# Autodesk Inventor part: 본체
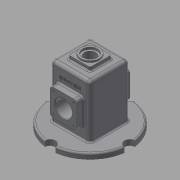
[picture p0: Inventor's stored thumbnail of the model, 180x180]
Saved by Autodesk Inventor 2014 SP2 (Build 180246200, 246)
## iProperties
Created: 2018-07
Part Number: 본체
Material: Generic
Document SubType Name: Modeling
Designer: 거성
Density: 1 g/cm^3
Appearance: Default
Author: 거성
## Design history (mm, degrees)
sketch "스케치1"
  geometry: L1 (-37, 37)-(37, 37); L2 (37, 37)-(37, -37); L3 (37, -37)-(-37, -37); L4 (-37, -37)-(-37, 37); 3 further points
  constraints: 8 end point, 2 midpoint, 2 parallel, 1 horizontal, 1 horizontal alignment, 1 perpendicular, 1 vertical alignment
  dimensions: "d0" = 74 distance of L1.start L1.end; "d1" = 74 distance of L1.end L2.end
extrude "돌출1" new body sketch "스케치1" distance "d2" = 110; taper "d3" = 0 deg
feature "쉘1" dims "d4" = 5
node "작업 평면1"
sketch "스케치2"
  geometry: L1 (-20, 20)-(20, 20); L2 (20, 20)-(20, -20); L3 (20, -20)-(-20, -20); L4 (-20, -20)-(-20, 20); 3 further points
  constraints: 8 end point, 2 midpoint, 2 parallel, 1 horizontal, 1 horizontal alignment, 1 perpendicular, 1 vertical alignment
  dimensions: "d6" = 40 distance of L1.start L1.end; "d7" = 40 distance of L1.end L2.end
extrude "돌출2" join sketch "스케치2" stored distance "d8" = 10; taper "d9" = 0 deg
sketch "스케치3"
  geometry: C1 r 17.5 at (0, 0); 1 further point
  constraints: 1 centre point, 1 coincident
  dimensions: "d10" = 35 diameter of C1
extrude "돌출3" join sketch "스케치3" distance "d11" = 3; taper "d12" = 0 deg
hole "구멍1" diameter "d15" = 21; stored, may be unused: countersink angle "d19" = 90 deg, drill point angle "d21" = 0 deg; dims "d13" = 10, "d14" = 10, "d16" = 6, "d17" = 28, "d18" = 4, "d20" = 20
sketch "스케치4"
  geometry: L1 (37, 37)-(-37, 37) reference; L2 (32, -32)-(32, 32) reference; L3 (32, 32)-(-32, 32) reference; L4 (-32, 32)-(-32, -32) reference; L5 (-32, -32)-(32, -32) reference; L6 (37, 37)-(37, -37) reference; L7 (37, -37)-(-37, -37) reference; L8 (-37, -37)-(-37, 37) reference; L9 (-37, 37)-(37, 37) reference; C1 r 75 at (0, 0); 1 further point
  constraints: 1 centre point, 1 coincident
  dimensions: "d22" = 150 diameter of C1
extrude "돌출4" join sketch "스케치4" distance "d23" = 10; taper "d24" = 0 deg
sketch "스케치5"
  geometry: L1 (0, 74)-(100, 74) reference; L2 (30, 62)-(80, 62); L3 (80, 62)-(80, 12); L4 (80, 12)-(30, 12); L5 (30, 12)-(30, 62); L6 (110, 112)-(110, -38) reference; 1 further point
  constraints: 8 end point, 2 parallel, 1 horizontal, 1 perpendicular
  dimensions: "d25" = 50 distance of L2.start L2.end; "d26" = 50 distance of L4.end L2.start; "d27" = 30 distance between parallel lines of L3 L6; "d28" = 12 distance between parallel lines of L2 L1
extrude "돌출5" join sketch "스케치5" distance "d29" = 13; taper "d30" = 0 deg
sketch "스케치6"
  geometry: L1 (-105, 0)-(-105, 64) reference; L2 (5, 69)-(-95, 69) reference; C1 r 25 at (-50, 32); 1 further point
  constraints: 1 centre point
  dimensions: "d31" = 55 distance from line of C1.centre L1; "d32" = 37 distance from line of C1.centre L2; "d33" = 50 diameter of C1
extrude "돌출6" join sketch "스케치6" distance "d34" = 7; taper "d35" = -20 deg
sketch "스케치7"
  geometry: C1 r 25 at (55, 37) reference; C2 r 16 at (55, 37); 1 further point
  constraints: 1 centre point, 1 coincident
  dimensions: "d36" = 32 diameter of C2
extrude "돌출7" cut sketch "스케치7" stored distance "d37" = 7; taper "d38" = 0 deg
sketch "스케치8"
  geometry: L1 (37, 37)-(-37, 37) reference; L2 (0, 2.478)-(0, 75); C1 r 10 at (0, 75); 1 further point
  constraints: 2 end point, 2 vertical alignment, 1 centre point, 1 coincident, 1 perpendicular, 1 other
  dimensions: "d39" = 20 diameter of C1
extrude "돌출8" cut sketch "스케치8" stored distance "d40" = 7; taper "d41" = 0 deg
sketch "스케치9"
  geometry: L1 (80, 62)-(30, 62) reference; L2 (30, 62)-(30, 12) reference; L3 (30, 12)-(80, 12) reference; L4 (80, 12)-(80, 62) reference; 5 further points
  constraints: 2 horizontal alignment, 2 vertical alignment
  dimensions: "d45" = 6 distance from line of point (36, 56) L1; "d46" = 6 distance from line of L2 point (36, 56); "d47" = 6 distance from line of L3 point (36, 18); "d48" = 6 distance from line of L4 point (74, 56)
hole "구멍2" sketch "스케치9" at (36, 56), (74, 56), (74, 18), (36, 18) diameter "d49" = 3.242; stored, may be unused: countersink angle "d53" = 90 deg, drill point angle "d55" = 118 deg; dims "d50" = 8, "d51" = 28, "d52" = 4, "d54" = 10
fillet "모깎기1" dims "d56" = 6
fillet "모깎기2" dims "d57" = 3
fillet "모깎기3" dims "d58" = 6
fillet "모깎기4" dims "d59" = 3
fillet "모깎기5" dims "d60" = 3
sketch "스케치10"
  geometry: L1 (16, 13.5)-(16, 48.5) reference; 2 further points
  constraints: 1 horizontal alignment, 1 other
  dimensions: "d61" = 30 distance from line of L1 point (-14, 31)
feature "엠보싱1" sketch "스케치10" dims "d0" = 74, "d1" = 74, "d62" = 0.5, "d63" = 0
chamfer "모따기1" distance "d64" = 1; stored, may be unused: second distance "d65" = 2, angle "d66" = 45 deg
node "솔리드1"
mirror "대칭1"
pattern_circular "원형 패턴1" dims angle "d43" = 360 deg
mirror "대칭2"
node "절단 모서리 투영1"
other parameters: "d5" = -117
